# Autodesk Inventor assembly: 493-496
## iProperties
Author: Administrator
Created: 2002-03
Part Number: 493-496
Document SubType Name: Assembly
Designer: Administrator
Control State: 0
Master: False
Checked Out: False
PropertySet Name: Design Tracking Control
Shininess: 64.0
Angle Display Precision: 2
Document Length Units: 11272
Document Angle Units: 11286
Document Time Units: 11279
Document Mass Units: 11290
Document Length Units Precision: 3
Document Angle Units Precision: 2
Compacted: True
PropertySet Name: _Private Model Information
Density: 0.0
Volumn: 0.0
Area: 0.0
PropertySet Name: Model Information
